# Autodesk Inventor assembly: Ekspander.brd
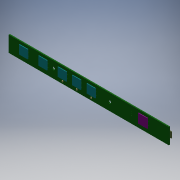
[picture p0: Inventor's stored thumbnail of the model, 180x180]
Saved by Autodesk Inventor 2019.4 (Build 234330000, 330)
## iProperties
Created: 2019-11
Part Number: Ekspander.brd
Document SubType Name: Assembly
Designer: Willist
Author: Willist
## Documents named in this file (10)
- D:\Biblioteki\Dokumenty\,Studia\StudiaMagisterskie\Semestry\Semestr2\ProjektGupowy\GIT\Projekt-Grupowy-Minutnik\Minutnix\3d\Ekspander.brd.iam
- D:\Biblioteki\Dokumenty\,Studia\StudiaMagisterskie\Semestry\Semestr2\ProjektGupowy\GIT\Projekt-Grupowy-Minutnik\Minutnix\3d\Ekspander.brd_Outline.ipt
- D:\Biblioteki\Dokumenty\,Studia\StudiaMagisterskie\Semestry\Semestr2\ProjektGupowy\GIT\Projekt-Grupowy-Minutnik\Minutnix\3d\C0402, C0402_1.ipt
- D:\Biblioteki\Dokumenty\,Studia\StudiaMagisterskie\Semestry\Semestr2\ProjektGupowy\GIT\Projekt-Grupowy-Minutnik\Minutnix\3d\TACTILE_SWITCH_PTH_12MM, MOMENTARY-SWITCH-SPST-PTH-12MM_3.ipt
- D:\Biblioteki\Dokumenty\,Studia\StudiaMagisterskie\Semestry\Semestr2\ProjektGupowy\GIT\Projekt-Grupowy-Minutnik\Minutnix\3d\R0603, R0603_5.ipt
- D:\Biblioteki\Dokumenty\,Studia\StudiaMagisterskie\Semestry\Semestr2\ProjektGupowy\GIT\Projekt-Grupowy-Minutnik\Minutnix\3d\CHIPLED_0805, CHIPLED_0805_7.ipt
- D:\Biblioteki\Dokumenty\,Studia\StudiaMagisterskie\Semestry\Semestr2\ProjektGupowy\GIT\Projekt-Grupowy-Minutnik\Minutnix\3d\ROTARY_ENC_PLAIN, ENCODER-SWITCH_12.ipt
- D:\Biblioteki\Dokumenty\,Studia\StudiaMagisterskie\Semestry\Semestr2\ProjektGupowy\GIT\Projekt-Grupowy-Minutnik\Minutnix\3d\47589-0002, MICRO-USB-RECEPTACLE_15.ipt
- D:\Biblioteki\Dokumenty\,Studia\StudiaMagisterskie\Semestry\Semestr2\ProjektGupowy\GIT\Projekt-Grupowy-Minutnik\Minutnix\3d\FH12-12S-0_5SH_THINER, FH12-12S-0_5S_THINNER_19.ipt
- D:\Biblioteki\Dokumenty\,Studia\StudiaMagisterskie\Semestry\Semestr2\ProjektGupowy\GIT\Projekt-Grupowy-Minutnik\Minutnix\3d\JST-XH-03-PACKAGE-LONG-PAD, JST-XH-03-PIN-LONG-PAD_21.ipt
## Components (15 placed, 15 different names)
1. Ekspander.brd_Outline:1
2. C4_2
3. COUNTER_4
4. L1_6
5. L_COUNTER_8
6. L_VOLUME_9
7. L_WARNING_10
8. PLAY_PAUSE_11
9. S11_13
10. STOP_RESET_14
11. U_1_16
12. VOLUME_17
13. WARNING_18
14. X1_20
15. X6_22
